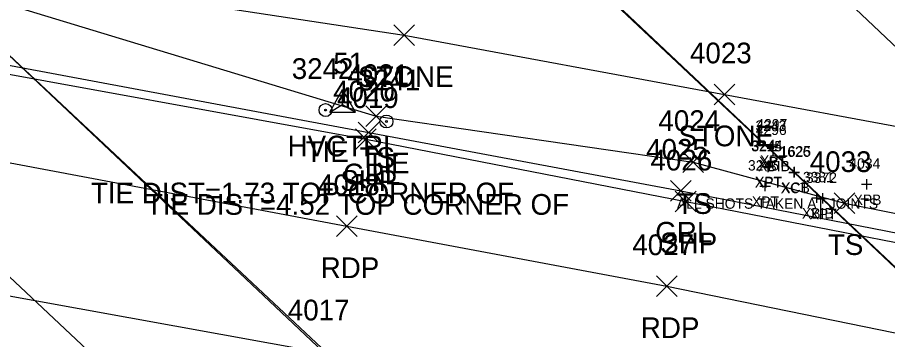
# Model space of a CAD drawing. Extents: x 1647574 to 1652703, y 212895 to 228670.
# Drawn here: x 1648950.8 to 1649034.7, y 227138.6 to 227169.7 of the extents above; entities that cross this region are included whole.
import ezdxf

# ---------------------------------------------------------------- set-up
doc = ezdxf.new("R2010")
doc.units = 0
for name, color, linetype in [('B_A', 7, 'Continuous'), ('B_C', 7, 'Continuous'), ('B_I', 7, 'Continuous'), ('B_TIC', 7, 'Continuous'), ('BDC', 7, 'Continuous'), ('BELB', 7, 'Continuous'), ('C_A', 7, 'Continuous'), ('C_C', 7, 'Continuous'), ('C_I', 7, 'Continuous'), ('CBP', 7, 'Continuous'), ('CPSM', 7, 'Continuous'), ('L_A', 7, 'Continuous'), ('L_I', 7, 'Continuous'), ('L_TIC', 7, 'Continuous'), ('LASF', 7, 'Continuous'), ('LELB', 7, 'Continuous'), ('P_A', 7, 'Continuous'), ('P_I', 7, 'Continuous'), ('P_TIC', 7, 'Continuous'), ('PET', 7, 'Continuous'), ('PRC', 7, 'Continuous'), ('PSP', 7, 'Continuous'), ('R_A', 7, 'Continuous'), ('R_I', 7, 'Continuous'), ('R_TIC', 7, 'Continuous'), ('RGR', 7, 'Continuous')]:
    doc.layers.add(name, color=color, linetype=linetype)

msp = doc.modelspace()

# ---------------------------------------------------------------- linework, layer by layer
at = {"layer": 'B_TIC'}
for p, q in [((1649023.623, 227157.262), (1649023.698, 227157.262)), ((1649023.682, 227156.867), (1649023.758, 227156.867)), ((1649023.707, 227157.402), (1649023.782, 227157.402)), ((1649023.214, 227155.285), (1649023.29, 227155.285)), ((1649023.239, 227155.342), (1649023.314, 227155.342)), ((1649025.713, 227154.751), (1649025.789, 227154.751)), ((1649025.744, 227154.791), (1649025.82, 227154.791)), ((1649032.72, 227153.617), (1649032.795, 227153.617)), ((1649022.927, 227153.438), (1649023.002, 227153.438)), ((1649027.911, 227152.31), (1649027.986, 227152.31)), ((1649028.502, 227152.245), (1649028.578, 227152.245))]:
    msp.add_line(p, q, dxfattribs=at)
for points in [[(1649023.619, 227156.762), (1649023.619, 227157.762)], [(1649023.703, 227156.902), (1649023.703, 227157.902)], [(1649023.119, 227157.262), (1649024.119, 227157.262)], [(1649023.179, 227156.867), (1649024.179, 227156.867)], [(1649023.203, 227157.402), (1649024.203, 227157.402)], [(1649023.679, 227156.367), (1649023.679, 227157.367)], [(1649022.711, 227155.285), (1649023.711, 227155.285)], [(1649022.735, 227155.342), (1649023.735, 227155.342)], [(1649023.211, 227154.785), (1649023.211, 227155.785)], [(1649023.235, 227154.842), (1649023.235, 227155.842)], [(1649025.71, 227154.251), (1649025.71, 227155.251)], [(1649025.741, 227154.291), (1649025.741, 227155.291)], [(1649025.21, 227154.751), (1649026.21, 227154.751)], [(1649025.241, 227154.791), (1649026.241, 227154.791)], [(1649022.923, 227152.938), (1649022.923, 227153.938)], [(1649032.216, 227153.617), (1649033.216, 227153.617)], [(1649032.716, 227153.117), (1649032.716, 227154.117)], [(1649022.423, 227153.438), (1649023.423, 227153.438)], [(1649027.907, 227151.81), (1649027.907, 227152.81)], [(1649028.499, 227151.745), (1649028.499, 227152.745)], [(1649027.407, 227152.31), (1649028.407, 227152.31)], [(1649027.999, 227152.245), (1649028.999, 227152.245)]]:
    msp.add_lwpolyline(points, dxfattribs=at)
at = {"layer": 'BDC'}
for points in [[(1648705.852, 227396.154), (1648745.059, 227359.411), (1648787.916, 227318.711), (1648830.863, 227278.3), (1648888.33, 227224.067), (1648945.958, 227169.85), (1649010.577, 227108.866), (1649057.241, 227064.803), (1649099.962, 227024.603)], [(1648705.902, 227396.256), (1648745.142, 227359.215), (1648788.072, 227318.717), (1648831.078, 227278.232), (1648888.572, 227223.976), (1648945.897, 227169.932), (1649010.764, 227109.119), (1649057.374, 227064.845), (1649100.019, 227024.673)], [(1649190.777, 226999.084), (1649140.468, 227046.558), (1649090.33, 227093.733), (1649025.71, 227154.751), (1648968.186, 227208.898), (1648910.789, 227263.155), (1648860.431, 227310.794), (1648808.664, 227359.741)], [(1649190.944, 226999.114), (1649140.59, 227046.719), (1649090.397, 227093.864), (1649025.741, 227154.791), (1648968.355, 227208.988), (1648910.836, 227263.351), (1648860.59, 227310.809), (1648808.767, 227359.651)]]:
    msp.add_lwpolyline(points, dxfattribs=at)
at = {"layer": 'BELB'}
for points in [[(1648676.128, 227401.909), (1648716.738, 227364.514), (1648759.552, 227324.27), (1648803.456, 227283.214), (1648860.317, 227229.513), (1648917.836, 227175.012), (1648982.231, 227114.435), (1649029.643, 227069.952), (1649071.001, 227030.272)], [(1649218.046, 226994.506), (1649168.124, 227041.655), (1649117.675, 227088.79), (1649053.801, 227149.566), (1648996.598, 227203.697), (1648938.733, 227258.119), (1648889.571, 227305.276), (1648838.072, 227353.54)]]:
    msp.add_lwpolyline(points, dxfattribs=at)
at = {"layer": 'CBP'}
for centre, radius in [((1648980.542, 227160.77), 0.625), ((1648980.542, 227160.77), 0.0833), ((1648986.412, 227159.669), 0.625), ((1648986.412, 227159.669), 0.0833)]:
    msp.add_circle(centre, radius, dxfattribs=at)
at = {"layer": 'CPSM'}
for p, q in [((1648980.94, 227160.58), (1648982.19, 227162.745)), ((1648983.44, 227160.58), (1648982.19, 227162.745)), ((1648982.191, 227161.301), (1648982.19, 227162.745)), ((1648980.94, 227160.58), (1648982.191, 227161.301)), ((1648982.191, 227161.301), (1648982.191, 227161.301)), ((1648982.191, 227161.301), (1648983.44, 227160.58)), ((1648980.94, 227160.58), (1648983.44, 227160.58))]:
    msp.add_line(p, q, dxfattribs=at)
at = {"layer": 'L_TIC'}
for points in [[(1648987.129, 227166.991), (1648989.129, 227168.991)], [(1648989.129, 227166.991), (1648987.129, 227168.991)], [(1649018.013, 227161.278), (1649020.013, 227163.278)], [(1649020.013, 227161.278), (1649018.013, 227163.278)], [(1648984.415, 227159.185), (1648986.415, 227161.185)], [(1648986.415, 227159.185), (1648984.415, 227161.185)], [(1649014.972, 227154.751), (1649016.972, 227156.751)], [(1649016.972, 227154.751), (1649014.972, 227156.751)], [(1649029.56, 227150.792), (1649031.56, 227152.792)], [(1649031.56, 227150.792), (1649029.56, 227152.792)]]:
    msp.add_lwpolyline(points, dxfattribs=at)
at = {"layer": 'LASF'}
msp.add_lwpolyline([(1648591.009, 227270.343), (1648624.693, 227258.455), (1648664.933, 227242.862), (1648702.926, 227233.816), (1648737.154, 227219.4), (1648772.089, 227211.83), (1648798.883, 227202.714), (1648829.377, 227195.595), (1648870.643, 227189.301), (1648888.064, 227189.998), (1648910.238, 227184.26), (1648945.065, 227174.552), (1648988.129, 227167.991), (1649019.013, 227162.278), (1649093.93, 227148.389), (1649131.468, 227140.127), (1649155.823, 227137.226), (1649206.951, 227127.276), (1649258.232, 227116.863), (1649289.141, 227114.771), (1649313.58, 227109.451)], dxfattribs=at)
at = {"layer": 'LELB'}
msp.add_lwpolyline([(1648597.273, 227264.486), (1648633.73, 227250.634), (1648664.389, 227240.318), (1648701.872, 227228.729), (1648735.461, 227216.545), (1648770.192, 227206.754), (1648796.996, 227200.241), (1648829.006, 227192.504), (1648869.112, 227184.885), (1648887.117, 227184.175), (1648909.076, 227180.513), (1648944.404, 227172.664), (1648985.415, 227160.185), (1649015.972, 227155.751), (1649030.56, 227151.792), (1649075.874, 227142.707), (1649094.964, 227142.334), (1649128.793, 227137.178), (1649163.599, 227126.992), (1649206.12, 227120.023), (1649254.696, 227110.714), (1649288.497, 227104.847), (1649312.044, 227099.384)], dxfattribs=at)
at = {"layer": 'P_TIC'}
for points in [[(1648983.425, 227156.969), (1648985.425, 227158.969)], [(1648985.425, 227156.969), (1648983.425, 227158.969)], [(1649014.263, 227150.943), (1649016.263, 227152.943)], [(1649016.263, 227150.943), (1649014.263, 227152.943)], [(1648981.588, 227148.559), (1648983.588, 227150.559)], [(1648983.588, 227148.559), (1648981.588, 227150.559)], [(1649012.451, 227142.774), (1649014.451, 227144.774)], [(1649014.451, 227142.774), (1649012.451, 227144.774)]]:
    msp.add_lwpolyline(points, dxfattribs=at)
at = {"layer": 'PET'}
msp.add_lwpolyline([(1648582.821, 227256.084), (1648618.147, 227242.999), (1648661.462, 227228.082), (1648697.31, 227216.445), (1648732, 227205.65), (1648767.283, 227195.85), (1648794.922, 227188.715), (1648824.663, 227181.318), (1648870.225, 227171.495), (1648904.553, 227164.504), (1648941.404, 227157.321), (1648982.588, 227149.559), (1649013.451, 227143.774), (1649051.482, 227136.017), (1649092.559, 227128.28), (1649129.41, 227121.264), (1649164.129, 227114.968), (1649203.067, 227107.319), (1649253.119, 227097.953), (1649285.33, 227091.532), (1649309.805, 227086.858)], dxfattribs=at)
at = {"layer": 'PRC'}
msp.add_lwpolyline([(1648578.474, 227245.088), (1648614.144, 227232.377), (1648658.376, 227217.212), (1648693.17, 227205.447), (1648728.772, 227194.614), (1648764.162, 227184.595), (1648791.485, 227177.326), (1648822.259, 227169.584), (1648868.208, 227159.379), (1648902.01, 227152.53), (1648938.677, 227144.922), (1648979.678, 227137.482), (1649011.638, 227131.497), (1649049.006, 227124.369), (1649090.363, 227116.947), (1649126.936, 227110.347), (1649164.154, 227103.487), (1649199.467, 227096.77), (1649251.628, 227086.358), (1649284.276, 227080.21), (1649307.757, 227075.596)], dxfattribs=at)
at = {"layer": 'PSP'}
msp.add_lwpolyline([(1648480.186, 227300.935), (1648523.095, 227287.235), (1648552.393, 227275.528), (1648583.82, 227263.797), (1648620.778, 227250.204), (1648663.69, 227235.815), (1648700.093, 227224.251), (1648734.52, 227213.948), (1648769.769, 227204.03), (1648796.828, 227197.07), (1648827.571, 227189.553), (1648872.239, 227179.077), (1648906.708, 227172.293), (1648943.109, 227165.503), (1648984.425, 227157.969), (1649015.263, 227151.943), (1649051.882, 227144.802), (1649094.443, 227136.72), (1649131.243, 227129.788), (1649164.299, 227122.927), (1649204.314, 227115.136), (1649254.536, 227105.699), (1649286.332, 227099.339), (1649311.67, 227094.73)], dxfattribs=at)
at = {"layer": 'R_TIC'}
for points in [[(1648983.701, 227157.6), (1648985.701, 227159.6)], [(1648985.701, 227157.6), (1648983.701, 227159.6)], [(1649013.789, 227151.98), (1649015.789, 227153.98)], [(1649015.789, 227151.98), (1649013.789, 227153.98)]]:
    msp.add_lwpolyline(points, dxfattribs=at)
at = {"layer": 'RGR'}
msp.add_lwpolyline([(1648874.676, 227180.08), (1648907.143, 227173.269), (1648943.277, 227166.367), (1648984.701, 227158.6), (1649014.789, 227152.98), (1649051.86, 227145.733), (1649094.582, 227137.658), (1649131.359, 227130.713), (1649164.131, 227124.406), (1649204.957, 227116.676), (1649254.392, 227107.302), (1649286.862, 227101.106), (1649311.642, 227096.214)], dxfattribs=at)

# ---------------------------------------------------------------- texts
at = {"layer": 'B_A'}
for s, p in [('XPT', (1649022.34, 227155.262)), ('XPT', (1649022.424, 227155.402)), ('XBIB', (1649022.25, 227154.867)), ('XPT', (1649021.956, 227153.342)), ('XPT', (1649021.931, 227153.285)), ('XCT', (1649024.43, 227152.751)), ('XCB', (1649024.477, 227152.791)), ('XPB', (1649031.452, 227151.617)), ('XPT', (1649021.644, 227151.438)), ('XBIB', (1649026.478, 227150.31)), ('XPT', (1649027.219, 227150.245))]:
    msp.add_text(s, height=1, dxfattribs=at).set_placement(p)
at = {"layer": 'B_C'}
msp.add_text('ALL SHOTS TAKEN AT JOINTS', height=1, dxfattribs=at).set_placement((1649014.419, 227151.251))
at = {"layer": 'B_I'}
for s, p in [('3243', (1649021.989, 227158.762)), ('4296', (1649022.022, 227158.367)), ('4297', (1649022.073, 227158.902)), ('3245', (1649021.581, 227156.785)), ('3244', (1649021.605, 227156.842)), ('1626', (1649024.312, 227156.251)), ('1625', (1649024.371, 227156.291)), ('4034', (1649031.047, 227155.117)), ('3246', (1649021.266, 227154.938)), ('3381', (1649026.561, 227153.81)), ('3372', (1649026.869, 227153.745))]:
    msp.add_text(s, height=1, dxfattribs=at).set_placement(p)
at = {"layer": 'C_A'}
for s, p in [('HVCTRL', (1648976.884, 227156.301)), ('TIE', (1648978.621, 227155.77)), ('TIE', (1648984.491, 227154.669))]:
    msp.add_text(s, height=2, dxfattribs=at).set_placement(p)
at = {"layer": 'C_C'}
for s, p in [('TIE DIST=1.73 TOP CORNER OF', (1648957.921, 227151.77)), ('TIE DIST=4.52 TOP CORNER OF', (1648963.223, 227150.669))]:
    msp.add_text(s, height=2, dxfattribs=at).set_placement(p)
at = {"layer": 'C_I'}
for s, p in [('51', (1648981.293, 227164.301)), ('3242', (1648977.282, 227163.77)), ('3241', (1648983.719, 227162.669))]:
    msp.add_text(s, height=2, dxfattribs=at).set_placement(p)
at = {"layer": 'L_A'}
for s, p in [('STONE', (1648983.673, 227162.991)), ('STONE', (1649014.556, 227157.278)), ('TS', (1648983.824, 227155.185)), ('TS', (1649014.381, 227150.751)), ('TS', (1649028.97, 227146.792))]:
    msp.add_text(s, height=2, dxfattribs=at).set_placement(p)
at = {"layer": 'L_I'}
for s, p in [('4023', (1649015.674, 227165.278)), ('4021', (1648982.643, 227163.185)), ('4024', (1649012.633, 227158.751)), ('4033', (1649027.222, 227154.792))]:
    msp.add_text(s, height=2, dxfattribs=at).set_placement(p)
at = {"layer": 'P_A'}
for s, p in [('SHP', (1648981.961, 227152.969)), ('SHP', (1649012.798, 227146.943)), ('RDP', (1648980.076, 227144.559)), ('RDP', (1649010.939, 227138.774))]:
    msp.add_text(s, height=2, dxfattribs=at).set_placement(p)
at = {"layer": 'P_I'}
for s, p in [('4019', (1648981.646, 227160.969)), ('4026', (1649011.869, 227154.943)), ('4018', (1648979.816, 227152.559)), ('4027', (1649010.113, 227146.774)), ('4017', (1648976.907, 227140.482))]:
    msp.add_text(s, height=2, dxfattribs=at).set_placement(p)
at = {"layer": 'R_A'}
for p in [(1648982.245, 227153.6), (1649012.332, 227147.98)]:
    msp.add_text('GRL', height=2, dxfattribs=at).set_placement(p)
at = {"layer": 'R_I'}
for s, p in [('4020', (1648981.276, 227161.6)), ('4025', (1649011.451, 227155.98))]:
    msp.add_text(s, height=2, dxfattribs=at).set_placement(p)

doc.saveas('drawing.dxf')
